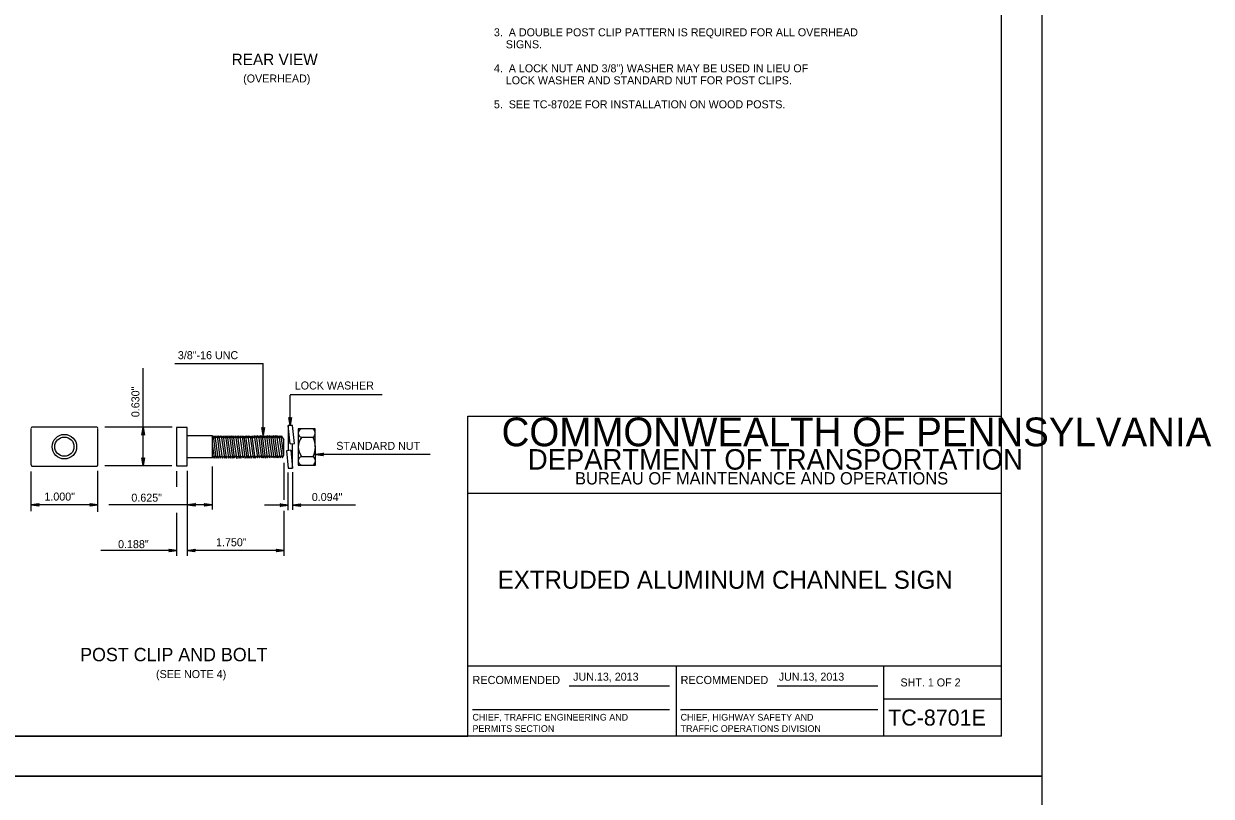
# Model space of a CAD drawing. Extents: x 647822 to 649292, y 298458 to 299646.
# Drawn here: x 648281.8 to 648726.9, y 299044.1 to 299333.8 of the extents above; entities that cross this region are included whole.
import ezdxf

# ---------------------------------------------------------------- set-up
doc = ezdxf.new("R2010")
doc.units = 0
for name, color, linetype in [('1', 7, 'Continuous'), ('2', 7, 'Continuous'), ('3', 7, 'Continuous'), ('XCS-GRID-MIN', 7, 'Continuous')]:
    doc.layers.add(name, color=color, linetype=linetype)

# ---------------------------------------------------------------- blocks, each defined once
blk = doc.blocks.new('RARROW')
at = {"layer": '3'}
blk.add_lwpolyline([(-2.2695, 0.285), (-2.184875, 0.12075), (0, 0), (-2.2695, 0.285), (-2.38575, 0.384625), (0, 0), (-2.183125, -0.108), (-2.262875, -0.2705), (0, 0), (-2.38575, -0.379125), (-2.262875, -0.2705)], dxfattribs=at)

msp = doc.modelspace()

# ---------------------------------------------------------------- linework, layer by layer
at = {"layer": '1'}
for p, q in [((648648.31, 299066.63), (648648.31, 299630.63)), ((648448.31, 299066.63), (648448.31, 299186.63)), ((648448.31, 299186.63), (648648.31, 299186.63)), ((648648.31, 299157.63), (648448.31, 299157.63)), ((648448.31, 299093), (648648.31, 299093)), ((648526.31, 299093), (648526.31, 299066.63)), ((648604.19, 299066.63), (648604.19, 299093)), ((648486.24, 299085.57), (648523.87, 299085.57)), ((648564.24, 299085.57), (648601.87, 299085.57)), ((648604.19, 299080.63), (648648.31, 299080.63)), ((648449.99, 299076.68), (648523.87, 299076.68)), ((648527.99, 299076.68), (648601.87, 299076.68)), ((648648.31, 299066.63), (647862.31, 299066.63)), ((647862.31, 299066.63), (648448.31, 299066.63))]:
    msp.add_line(p, q, dxfattribs=at)
at = {"layer": '2'}
for p, q in [((648326.55, 299168.07), (648326.55, 299204.71)), ((648338.38, 299206.34), (648371.53, 299206.34)), ((648371.53, 299179.44), (648371.53, 299206.34)), ((648416.12, 299194.69), (648381.71, 299194.69)), ((648381.71, 299183.19), (648381.71, 299194.57)), ((648284.53, 299182.07), (648284.53, 299168.44)), ((648309.15, 299182.57), (648284.9, 299182.57)), ((648309.53, 299168.44), (648309.53, 299182.07)), ((648337.4, 299182.57), (648312.15, 299182.57)), ((648339.03, 299182.44), (648339.03, 299168.07)), ((648343.03, 299182.44), (648339.03, 299182.44)), ((648343.03, 299168.07), (648343.03, 299182.44)), ((648382.58, 299183.19), (648380.96, 299183.19)), ((648381.64, 299176.29), (648380.96, 299183.19)), ((648380.96, 299183.19), (648380.96, 299173.68)), ((648383.25, 299176.45), (648382.58, 299183.19)), ((648384.65, 299181.94), (648384.65, 299168.32)), ((648391, 299181.94), (648384.65, 299181.94)), ((648391.17, 299168.32), (648391, 299181.94)), ((648343.03, 299179.44), (648352.46, 299179.44)), ((648352.46, 299179.44), (648352.46, 299171.07)), ((648352.46, 299179.44), (648352.46, 299171.07)), ((648352.46, 299178.57), (648352.88, 299179.32)), ((648352.46, 299176.32), (648353.15, 299171.07)), ((648353.98, 299171.07), (648352.88, 299179.32)), ((648352.88, 299179.32), (648353.15, 299178.57)), ((648353.15, 299178.57), (648353.56, 299179.32)), ((648354.66, 299171.07), (648353.56, 299179.32)), ((648353.56, 299179.32), (648353.98, 299178.57)), ((648353.98, 299178.57), (648354.39, 299179.44)), ((648354.39, 299179.44), (648354.8, 299178.57)), ((648355.49, 299171.07), (648354.39, 299179.32)), ((648354.8, 299178.57), (648355.21, 299179.32)), ((648356.31, 299171.07), (648355.08, 299179.32)), ((648355.21, 299179.32), (648355.49, 299178.69)), ((648355.49, 299178.69), (648355.9, 299179.32)), ((648357.14, 299171.07), (648355.9, 299179.32)), ((648355.9, 299179.32), (648356.31, 299178.57)), ((648356.31, 299178.57), (648356.73, 299179.32)), ((648357.83, 299171.07), (648356.73, 299179.32)), ((648356.73, 299179.32), (648357.14, 299178.57)), ((648357.14, 299178.57), (648357.55, 299179.32)), ((648358.65, 299171.07), (648357.55, 299179.32)), ((648357.55, 299179.32), (648357.96, 299178.57)), ((648357.96, 299178.57), (648358.24, 299179.32)), ((648359.48, 299171.07), (648358.24, 299179.32)), ((648358.24, 299179.32), (648358.65, 299178.57)), ((648358.65, 299178.57), (648359.06, 299179.32)), ((648360.16, 299171.07), (648359.06, 299179.32)), ((648359.06, 299179.32), (648359.34, 299178.57)), ((648359.34, 299178.57), (648359.75, 299179.32)), ((648360.85, 299171.07), (648359.75, 299179.32)), ((648359.75, 299179.32), (648360.16, 299178.57)), ((648360.16, 299178.57), (648360.44, 299179.32)), ((648361.68, 299171.07), (648360.44, 299179.32)), ((648360.44, 299179.32), (648360.85, 299178.57)), ((648360.85, 299178.57), (648361.26, 299179.32)), ((648362.5, 299171.07), (648361.26, 299179.32)), ((648361.26, 299179.32), (648361.68, 299178.57)), ((648361.68, 299178.57), (648362.09, 299179.32)), ((648363.19, 299171.07), (648362.09, 299179.32)), ((648362.09, 299179.32), (648362.5, 299178.57)), ((648362.5, 299178.57), (648362.91, 299179.32)), ((648364.01, 299171.07), (648362.91, 299179.32)), ((648362.91, 299179.32), (648363.33, 299178.57)), ((648363.33, 299178.57), (648363.74, 299179.32)), ((648364.84, 299171.07), (648363.74, 299179.32)), ((648363.74, 299179.32), (648364.01, 299178.57)), ((648364.01, 299178.57), (648364.43, 299179.32)), ((648364.43, 299179.32), (648364.84, 299178.57)), ((648365.53, 299170.94), (648364.43, 299179.19)), ((648364.84, 299178.57), (648365.11, 299179.32)), ((648366.21, 299171.07), (648365.11, 299179.32)), ((648365.11, 299179.32), (648365.66, 299178.57)), ((648365.66, 299178.57), (648365.94, 299179.44)), ((648365.94, 299179.44), (648366.35, 299178.57)), ((648367.04, 299171.07), (648365.94, 299179.32)), ((648366.35, 299178.57), (648366.76, 299179.32)), ((648366.76, 299179.32), (648367.04, 299178.57)), ((648367.86, 299170.94), (648366.76, 299179.19)), ((648367.04, 299178.57), (648367.45, 299179.32)), ((648367.45, 299179.32), (648367.86, 299178.57)), ((648368.55, 299170.94), (648367.45, 299179.19)), ((648367.86, 299178.57), (648368.28, 299179.32)), ((648368.14, 299178.94), (648368.28, 299179.44)), ((648369.51, 299171.19), (648368.28, 299179.44)), ((648368.28, 299179.44), (648368.69, 299178.69)), ((648368.69, 299178.69), (648369.1, 299179.44)), ((648368.69, 299178.69), (648369.1, 299179.44)), ((648369.1, 299179.44), (648369.51, 299178.69)), ((648370.2, 299171.07), (648369.1, 299179.32)), ((648369.51, 299178.69), (648369.79, 299179.44)), ((648369.79, 299179.44), (648370.2, 299178.69)), ((648371.03, 299171.07), (648369.93, 299179.32)), ((648370.2, 299178.69), (648370.61, 299179.44)), ((648371.71, 299171.19), (648370.61, 299179.44)), ((648370.61, 299179.44), (648371.03, 299178.57)), ((648371.03, 299178.57), (648371.3, 299179.44)), ((648371.3, 299179.44), (648371.71, 299178.57)), ((648372.4, 299170.94), (648371.3, 299179.32)), ((648371.71, 299178.57), (648372.13, 299179.44)), ((648372.13, 299179.44), (648372.54, 299178.69)), ((648373.23, 299171.07), (648372.13, 299179.32)), ((648372.54, 299178.69), (648372.95, 299179.44)), ((648372.95, 299179.44), (648373.36, 299178.69)), ((648374.05, 299171.07), (648372.95, 299179.32)), ((648373.36, 299178.69), (648373.64, 299179.44)), ((648373.64, 299179.44), (648374.19, 299178.69)), ((648374.88, 299171.07), (648373.64, 299179.32)), ((648374.19, 299178.69), (648374.46, 299179.44)), ((648374.46, 299179.44), (648374.88, 299178.57)), ((648375.7, 299171.07), (648374.46, 299179.32)), ((648374.88, 299178.57), (648375.15, 299179.44)), ((648375.15, 299179.44), (648375.7, 299178.69)), ((648376.39, 299171.07), (648375.15, 299179.32)), ((648375.7, 299178.69), (648375.98, 299179.44)), ((648375.98, 299179.44), (648376.39, 299178.69)), ((648377.08, 299171.07), (648375.98, 299179.32)), ((648376.39, 299178.69), (648376.8, 299179.44)), ((648377.9, 299171.19), (648376.66, 299179.44)), ((648376.8, 299179.44), (648377.21, 299178.57)), ((648377.21, 299178.57), (648377.49, 299179.44)), ((648377.49, 299179.44), (648377.9, 299178.69)), ((648378.73, 299171.07), (648377.49, 299179.32)), ((648377.9, 299178.69), (648378.31, 299179.32)), ((648378.31, 299179.32), (648379.28, 299177.82)), ((648379.28, 299172.07), (648378.31, 299179.32)), ((648379.28, 299171.94), (648379.28, 299177.82)), ((648381.64, 299176.29), (648383.25, 299176.45)), ((648382.58, 299167.19), (648382.58, 299176.45)), ((648390.4, 299178.69), (648385.9, 299178.69)), ((648381.94, 299173.84), (648380.33, 299173.68)), ((648380.33, 299173.68), (648380.96, 299167.19)), ((648381.94, 299173.84), (648382.58, 299167.19)), ((648390.28, 299171.44), (648385.9, 299171.44)), ((648434.08, 299172.32), (648391.12, 299172.32)), ((648284.9, 299167.94), (648309.15, 299167.94)), ((648337.28, 299168.07), (648312.15, 299168.07)), ((648339.03, 299168.07), (648343.03, 299168.07)), ((648352.46, 299171.07), (648343.03, 299171.07)), ((648344.4, 299170.94), (648344.4, 299170.94)), ((648352.46, 299167.77), (648352.46, 299151.6)), ((648353.29, 299170.94), (648353.29, 299171.07)), ((648379.4, 299155.27), (648379.4, 299169.19)), ((648380.96, 299167.19), (648382.58, 299167.19)), ((648384.65, 299168.32), (648391.17, 299168.32)), ((648391.15, 299169.82), (648391.03, 299169.82)), ((648284.65, 299151.02), (648284.65, 299165.94)), ((648309.53, 299150.74), (648309.53, 299166.19)), ((648339.15, 299160.17), (648339.15, 299165.97)), ((648343.15, 299134.23), (648343.15, 299166.19)), ((648380.96, 299151.39), (648380.96, 299165.57)), ((648382.71, 299151.51), (648382.71, 299165.69)), ((648309.53, 299153.42), (648284.65, 299153.42)), ((648352.46, 299153.42), (648313.74, 299153.42)), ((648352.46, 299153.42), (648343.03, 299153.42)), ((648339.15, 299134.23), (648339.15, 299150.45)), ((648380.96, 299153.26), (648372.01, 299153.26)), ((648379.4, 299134.23), (648379.4, 299151.12)), ((648406.21, 299153.26), (648382.71, 299153.26)), ((648339.15, 299136.23), (648310.66, 299136.23)), ((648379.4, 299136.23), (648343.03, 299136.23))]:
    msp.add_line(p, q, dxfattribs=at)
for points in [[(648352.46, 299171.07), (648352.74, 299171.82), (648353.15, 299170.94), (648353.56, 299171.82), (648353.98, 299170.94), (648354.39, 299171.82), (648354.66, 299170.94), (648355.08, 299171.69), (648355.49, 299170.94), (648355.9, 299171.69), (648356.31, 299170.94), (648356.59, 299171.69), (648357.14, 299170.94), (648357.41, 299171.82), (648357.83, 299170.94), (648358.24, 299171.69), (648358.65, 299170.94), (648358.93, 299171.82), (648359.48, 299170.94), (648359.75, 299171.69), (648360.16, 299170.94), (648360.58, 299171.82), (648360.85, 299171.07), (648361.26, 299171.82), (648361.68, 299170.82), (648362.09, 299171.82), (648362.5, 299170.94), (648362.78, 299171.82), (648363.19, 299170.94), (648363.6, 299171.82), (648364.01, 299171.07), (648364.43, 299171.69), (648364.84, 299170.94), (648365.11, 299171.69), (648365.53, 299170.94), (648365.94, 299171.82), (648366.21, 299170.94), (648366.76, 299171.69), (648367.04, 299170.94), (648367.45, 299171.82), (648367.86, 299171.07), (648368.28, 299171.69), (648368.55, 299170.94), (648368.96, 299171.82), (648369.24, 299171.19)], [(648369.1, 299171.69), (648369.38, 299171.07), (648369.79, 299171.94), (648370.2, 299171.07), (648370.61, 299171.82), (648371.03, 299171.07), (648371.3, 299171.94), (648371.71, 299171.07), (648372.13, 299171.94), (648372.4, 299170.94), (648372.95, 299171.94), (648373.23, 299171.07), (648373.64, 299171.94), (648374.05, 299171.07), (648374.33, 299171.94), (648374.88, 299171.19), (648375.15, 299171.82), (648375.7, 299171.07), (648375.98, 299171.82), (648376.39, 299171.07), (648376.66, 299171.94), (648377.08, 299171.07), (648377.63, 299171.82), (648377.9, 299171.07), (648378.18, 299171.94), (648378.73, 299171.07), (648379.28, 299172.07)]]:
    msp.add_lwpolyline(points, dxfattribs=at)
for radius in [4.6, 3.6]:
    msp.add_circle((648297.05, 299175.21), radius, dxfattribs=at)
for centre, radius, start, end in [((648386.36, 299180.31), 1.66, 104.9492, 255.0508), ((648388.97, 299180.27), 2.06, 310.6013, 49.3987), ((648390.48, 299175.14), 5.78, 141.8914, 218.1086), ((648382.49, 299175.09), 8.62, 335.1961, 24.8039), ((648386.31, 299169.9), 1.61, 103.5194, 256.4806), ((648389.14, 299169.92), 1.97, 305.7161, 54.2839)]:
    msp.add_arc(centre, radius, start, end, dxfattribs=at)
for centre, major_axis, start_param, end_param in [((648284.94, 299182.12), (0, 0.456), 0, 1.570796), ((648309.18, 299182.12), (0, 0.456), 4.712389, 6.283185), ((648284.94, 299168.41), (0, -0.456), 4.712389, 6.283185), ((648309.18, 299168.41), (0, -0.456), 0, 1.570796)]:
    msp.add_ellipse(centre, major_axis=major_axis, ratio=0.833333, start_param=start_param, end_param=end_param, dxfattribs=at)
at = {"layer": 'XCS-GRID-MIN'}
for points in [[(647822.31, 299645.63), (648663.31, 299645.63), (648663.31, 299051.63), (647822.31, 299051.63)], [(647822.31, 299051.63), (648663.31, 299051.63), (648663.31, 298457.63), (647822.31, 298457.63)]]:
    msp.add_lwpolyline(points, close=True, dxfattribs=at)

# ---------------------------------------------------------------- block references
at = {"layer": '2', "xscale": 1.2574347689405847, "yscale": 1.3092961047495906}
for p, rotation in [((648381.71, 299183.19), -90.00000000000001), ((648326.55, 299182.57), 89.99999999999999), ((648371.53, 299179.44), -90.00000000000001), ((648391.12, 299172.32), 180), ((648326.55, 299168.07), -90.00000000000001), ((648284.65, 299153.42), 180), ((648343.15, 299153.42), 180), ((648382.71, 299153.26), 180), ((648343.03, 299136.23), 180)]:
    msp.add_blockref('RARROW', p, dxfattribs=dict(at, rotation=rotation))
for p in [(648309.53, 299153.42), (648352.46, 299153.42), (648380.96, 299153.26), (648339.15, 299136.23), (648379.4, 299136.23)]:
    msp.add_blockref('RARROW', p, dxfattribs=at)

# ---------------------------------------------------------------- texts
at = {"layer": '1'}
for s, height, p in [('COMMONWEALTH OF PENNSYLVANIA', 10.7828, (648460.9, 299175.36)), ('DEPARTMENT OF TRANSPORTATION', 7.6837, (648470.76, 299166.61)), ('BUREAU OF MAINTENANCE AND OPERATIONS', 4.6253, (648488.41, 299161.04)), ('EXTRUDED ALUMINUM CHANNEL SIGN', 6.75, (648459.45, 299121.94)), ('RECOMMENDED', 3.048, (648449.99, 299086.2)), ('RECOMMENDED', 3.048, (648527.99, 299086.2)), ('SHT. 1 OF 2', 3, (648610.4, 299085.31)), ('CHIEF, TRAFFIC ENGINEERING AND', 2.5, (648449.99, 299072.51)), ('CHIEF, HIGHWAY SAFETY AND', 2.5, (648527.99, 299072.51)), ('TC-8701E', 6, (648605.79, 299070.63)), ('PERMITS SECTION', 2.5, (648449.99, 299068.26)), ('TRAFFIC OPERATIONS DIVISION', 2.5, (648527.99, 299068.26))]:
    msp.add_text(s, height=height, dxfattribs=at).set_placement(p)
at = {"layer": '2'}
for s, height, p in [('3.  A DOUBLE POST CLIP PATTERN IS REQUIRED FOR ALL OVERHEAD', 3, (648458.02, 299329.09)), ('    SIGNS.', 3, (648458.02, 299324.59)), ('REAR VIEW', 4.3, (648359.73, 299318.27)), ('4.  A LOCK NUT AND 3/8") WASHER MAY BE USED IN LIEU OF ', 3, (648458.02, 299315.59)), ('(OVERHEAD)', 3, (648364.05, 299311.77)), ('    LOCK WASHER AND STANDARD NUT FOR POST CLIPS.', 3, (648458.02, 299311.09)), ('5.  SEE TC-8702E FOR INSTALLATION ON WOOD POSTS.', 3, (648458.02, 299302.09)), ('3/8"-16 UNC', 3, (648339.58, 299208.02)), ('LOCK WASHER', 3, (648383.39, 299196.65)), ('STANDARD NUT', 3, (648398.94, 299174.02)), ('1.000"', 3, (648289.56, 299155)), ('0.094"', 3, (648389.77, 299154.84)), ('0.625"', 3, (648322.15, 299154.59)), ('0.188"', 3, (648317.17, 299137.17)), ('1.750"', 3, (648353.88, 299137.88)), ('POST CLIP AND BOLT', 5, (648302.96, 299094.76)), ('(SEE NOTE 4)', 3, (648331.4, 299088.44)), ('JUN.13, 2013', 3, (648487.71, 299087.46)), ('JUN.13, 2013', 3, (648564.78, 299087.46))]:
    msp.add_text(s, height=height, dxfattribs=at).set_placement(p)
msp.add_text('0.630"', height=3, rotation=90, dxfattribs=at).set_placement((648325.17, 299186.27))

doc.saveas('drawing.dxf')
